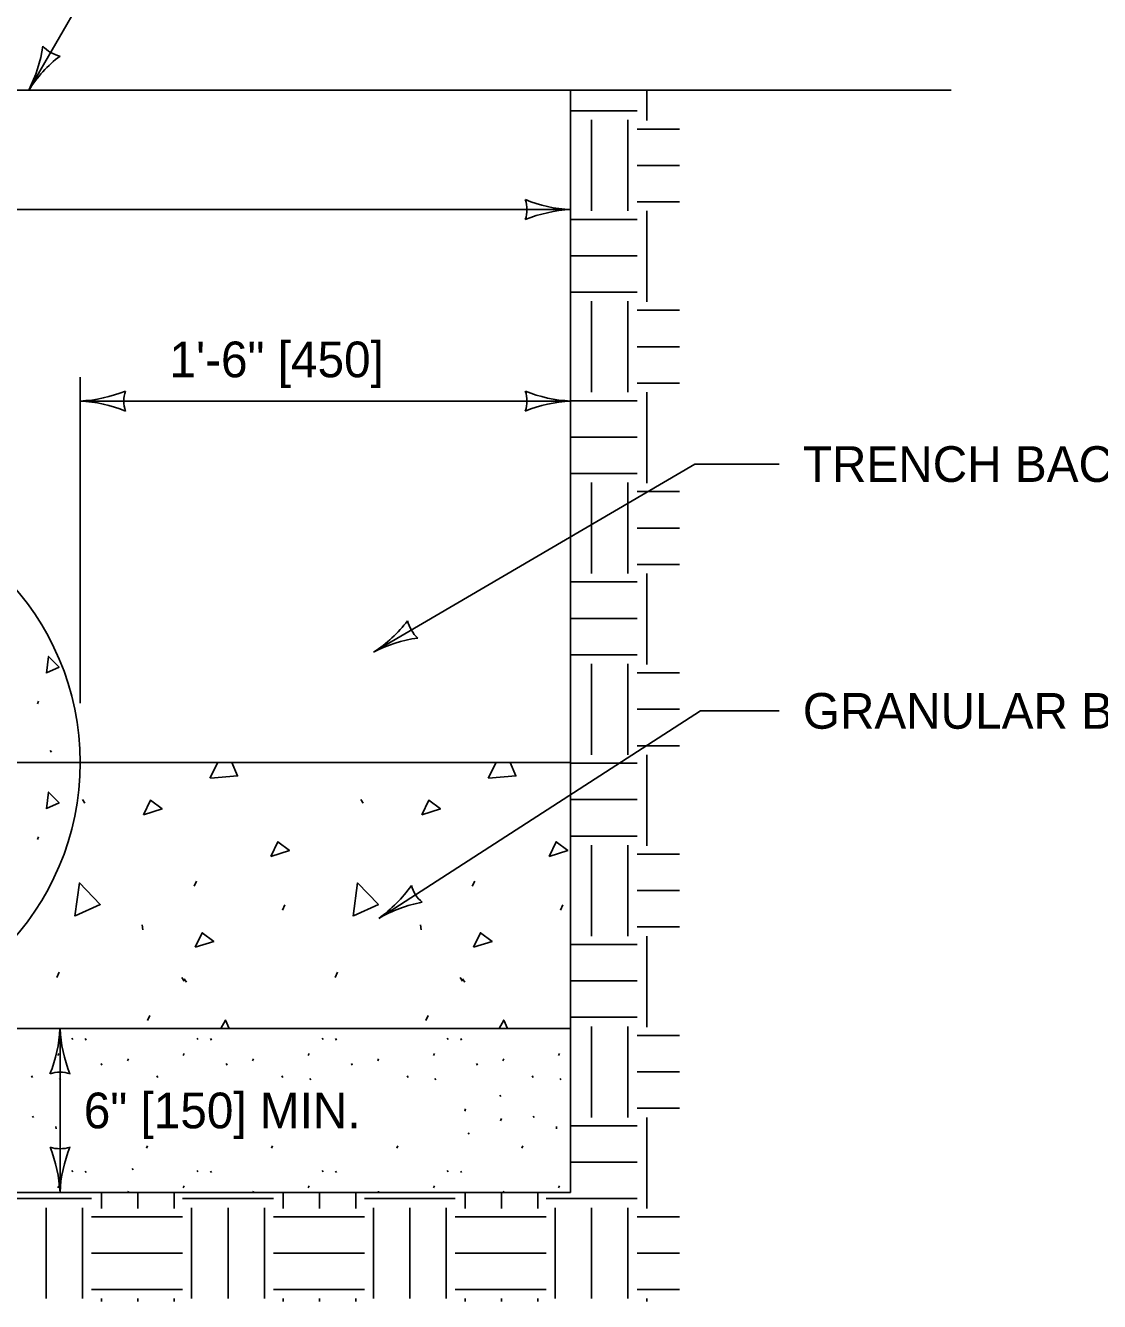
# Model space of a CAD drawing. Extents: x 49991.4 to 50061.4, y 49960.6 to 50011.4.
# Drawn here: x 50008.251 to 50010.057, y 49995.607 to 49997.751 of the extents above; entities that cross this region are included whole.
import ezdxf

# ---------------------------------------------------------------- set-up
doc = ezdxf.new("R2010")
doc.units = 0
for name, color, linetype in [('Level 1', 7, 'Continuous'), ('Level 2', 7, 'Continuous'), ('Level 3', 7, 'Continuous'), ('Level 5', 7, 'Continuous')]:
    doc.layers.add(name, color=color, linetype=linetype)

msp = doc.modelspace()

# ---------------------------------------------------------------- linework, layer by layer
at = {"layer": 'Level 1'}
for p, q in [((50009.8078, 49997.6424), (50005.9845, 49997.6424)), ((50009.1677, 49997.6424), (50009.1677, 49995.7899)), ((50009.296, 49997.6424), (50009.296, 49997.5913)), ((50009.1677, 49997.6076), (50009.2796, 49997.6076)), ((50009.2032, 49997.5923), (50009.2032, 49997.4395)), ((50009.2643, 49997.5923), (50009.2643, 49997.4395)), ((50009.2796, 49997.5771), (50009.351, 49997.5771)), ((50009.2796, 49997.5159), (50009.351, 49997.5159)), ((50009.2796, 49997.4548), (50009.351, 49997.4548)), ((50009.1677, 49997.4252), (50009.2796, 49997.4252)), ((50009.296, 49997.4395), (50009.296, 49997.2866)), ((50009.1677, 49997.3641), (50009.2796, 49997.3641)), ((50009.1677, 49997.3029), (50009.2796, 49997.3029)), ((50009.2032, 49997.2877), (50009.2032, 49997.1348)), ((50009.2643, 49997.2877), (50009.2643, 49997.1348)), ((50009.2796, 49997.2724), (50009.351, 49997.2724)), ((50009.2796, 49997.2112), (50009.351, 49997.2112)), ((50009.2796, 49997.1501), (50009.351, 49997.1501)), ((50009.296, 49997.1348), (50009.296, 49996.9819)), ((50009.1677, 49997.1205), (50009.2796, 49997.1205)), ((50009.1677, 49997.0594), (50009.2796, 49997.0594)), ((50009.1677, 49996.9982), (50009.2796, 49996.9982)), ((50009.2032, 49996.983), (50009.2032, 49996.8301)), ((50009.2643, 49996.983), (50009.2643, 49996.8301)), ((50009.2796, 49996.9677), (50009.351, 49996.9677)), ((50009.2796, 49996.9065), (50009.351, 49996.9065)), ((50009.2796, 49996.8454), (50009.351, 49996.8454)), ((50009.296, 49996.8301), (50009.296, 49996.6772)), ((50009.1677, 49996.8159), (50009.2796, 49996.8159)), ((50009.1677, 49996.7547), (50009.2796, 49996.7547)), ((50009.1677, 49996.6935), (50009.2796, 49996.6935)), ((50009.2032, 49996.6783), (50009.2032, 49996.5254)), ((50009.2643, 49996.6783), (50009.2643, 49996.5254)), ((50009.2796, 49996.663), (50009.351, 49996.663)), ((50008.2713, 49996.6112), (50008.2732, 49996.6156)), ((50009.2796, 49996.6018), (50009.351, 49996.6018)), ((50008.2928, 49996.5325), (50008.2947, 49996.5296)), ((50009.2796, 49996.5407), (50009.351, 49996.5407)), ((50009.296, 49996.5254), (50009.296, 49996.3725)), ((50008.3431, 49996.5122), (50009.1677, 49996.5122)), ((50008.561, 49996.4861), (50008.5748, 49996.5122)), ((50009.0289, 49996.4861), (50009.0427, 49996.5122)), ((50009.1677, 49996.5112), (50009.2796, 49996.5112)), ((50008.3471, 49996.45), (50008.351, 49996.4441)), ((50008.815, 49996.45), (50008.8189, 49996.4441)), ((50009.1677, 49996.45), (50009.2796, 49996.45)), ((50008.2713, 49996.3831), (50008.2732, 49996.3875)), ((50009.1677, 49996.3889), (50009.2796, 49996.3889)), ((50009.2032, 49996.3736), (50009.2032, 49996.2207)), ((50009.2643, 49996.3736), (50009.2643, 49996.2207)), ((50009.2796, 49996.3583), (50009.351, 49996.3583)), ((50008.5346, 49996.3044), (50008.5385, 49996.3132)), ((50009.0025, 49996.3044), (50009.0065, 49996.3132)), ((50009.2796, 49996.2971), (50009.351, 49996.2971)), ((50008.6831, 49996.2644), (50008.687, 49996.2732)), ((50009.151, 49996.2644), (50009.1549, 49996.2732)), ((50008.4474, 49996.2398), (50008.4484, 49996.231)), ((50008.9153, 49996.2398), (50008.9163, 49996.231)), ((50009.2796, 49996.236), (50009.351, 49996.236)), ((50009.1677, 49996.2065), (50009.2796, 49996.2065)), ((50009.296, 49996.2207), (50009.296, 49996.0678)), ((50008.3041, 49996.1511), (50008.308, 49996.1599)), ((50008.772, 49996.1511), (50008.7759, 49996.1599)), ((50008.5141, 49996.1511), (50008.518, 49996.1452)), ((50008.518, 49996.1488), (50008.5219, 49996.143)), ((50008.982, 49996.1511), (50008.9859, 49996.1452)), ((50008.9859, 49996.1488), (50008.9898, 49996.143)), ((50009.1677, 49996.1453), (50009.2796, 49996.1453)), ((50008.4565, 49996.0787), (50008.4604, 49996.0874)), ((50008.9244, 49996.0787), (50008.9283, 49996.0874)), ((50009.1677, 49996.0842), (50009.2796, 49996.0842)), ((50009.1677, 49996.0653), (50006.6247, 49996.0653)), ((50008.3291, 49996.0493), (50008.3307, 49996.0469)), ((50008.5396, 49996.0493), (50008.5412, 49996.0469)), ((50008.75, 49996.0493), (50008.7516, 49996.0469)), ((50008.9605, 49996.0493), (50008.9621, 49996.0469)), ((50009.1677, 49995.7899), (50009.1677, 49996.0653)), ((50009.2032, 49996.0689), (50009.2032, 49995.916)), ((50009.2643, 49996.0689), (50009.2643, 49995.916)), ((50009.2796, 49996.0536), (50009.351, 49996.0536)), ((50008.3517, 49996.0484), (50008.3533, 49996.046)), ((50008.5621, 49996.0484), (50008.5637, 49996.046)), ((50008.7726, 49996.0484), (50008.7742, 49996.046)), ((50008.983, 49996.0484), (50008.9846, 49996.046)), ((50008.3058, 49996.02), (50008.3074, 49996.0235)), ((50008.4225, 49996.0109), (50008.4241, 49996.0144)), ((50008.5163, 49996.02), (50008.5178, 49996.0235)), ((50008.6329, 49996.0109), (50008.6345, 49996.0144)), ((50008.7267, 49996.02), (50008.7283, 49996.0235)), ((50008.8434, 49996.0109), (50008.845, 49996.0144)), ((50008.9372, 49996.02), (50008.9387, 49996.0235)), ((50009.0538, 49996.0109), (50009.0554, 49996.0144)), ((50009.1476, 49996.02), (50009.1492, 49996.0235)), ((50008.2615, 49995.9856), (50008.2631, 49995.9832)), ((50008.3782, 49996.0063), (50008.3798, 49996.0039)), ((50008.4719, 49995.9856), (50008.4735, 49995.9832)), ((50008.5887, 49996.0063), (50008.5902, 49996.0039)), ((50008.6824, 49995.9856), (50008.684, 49995.9832)), ((50008.7991, 49996.0063), (50008.8007, 49996.0039)), ((50008.8928, 49995.9856), (50008.8944, 49995.9832)), ((50009.0096, 49996.0063), (50009.0111, 49996.0039)), ((50009.1033, 49995.9856), (50009.1049, 49995.9832)), ((50009.2796, 49995.9924), (50009.351, 49995.9924)), ((50008.3082, 49995.9813), (50008.3098, 49995.9789)), ((50008.7291, 49995.9813), (50008.7307, 49995.9789)), ((50008.9396, 49995.9813), (50008.9412, 49995.9789)), ((50009.15, 49995.9813), (50009.1516, 49995.9789)), ((50009.0486, 49995.9532), (50009.0502, 49995.9508)), ((50008.9898, 49995.9266), (50008.9913, 49995.9302)), ((50009.2796, 49995.9313), (50009.351, 49995.9313)), ((50008.263, 49995.9181), (50008.2646, 49995.9157)), ((50008.3021, 49995.9005), (50008.3025, 49995.8969)), ((50009.0499, 49995.9104), (50009.0515, 49995.914)), ((50009.1048, 49995.9181), (50009.1064, 49995.9157)), ((50009.1439, 49995.9005), (50009.1443, 49995.8969)), ((50009.1677, 49995.9018), (50009.2796, 49995.9018)), ((50009.296, 49995.916), (50009.296, 49995.7631)), ((50008.9955, 49995.89), (50008.9971, 49995.8876)), ((50008.4545, 49995.8645), (50008.4561, 49995.8681)), ((50008.665, 49995.8645), (50008.6666, 49995.8681)), ((50008.8754, 49995.8645), (50008.877, 49995.8681)), ((50009.0859, 49995.8645), (50009.0875, 49995.8681)), ((50009.1677, 49995.8406), (50009.2796, 49995.8406)), ((50008.3291, 49995.8267), (50008.3307, 49995.8243)), ((50008.3517, 49995.8258), (50008.3533, 49995.8234)), ((50008.4305, 49995.8302), (50008.4321, 49995.8278)), ((50008.5396, 49995.8267), (50008.5412, 49995.8243)), ((50008.5621, 49995.8258), (50008.5637, 49995.8234)), ((50008.75, 49995.8267), (50008.7516, 49995.8243)), ((50008.7726, 49995.8258), (50008.7742, 49995.8234)), ((50008.9605, 49995.8267), (50008.9621, 49995.8243)), ((50008.983, 49995.8258), (50008.9846, 49995.8234)), ((50008.3058, 49995.7974), (50008.3074, 49995.8009)), ((50008.5163, 49995.7974), (50008.5178, 49995.8009)), ((50008.7267, 49995.7974), (50008.7283, 49995.8009)), ((50008.9372, 49995.7974), (50008.9387, 49995.8009)), ((50009.1476, 49995.7974), (50009.1492, 49995.8009)), ((50009.1677, 49995.7899), (50006.6247, 49995.7899)), ((50006.6247, 49995.7899), (50009.1677, 49995.7899)), ((50008.2094, 49995.7795), (50008.3623, 49995.7795)), ((50008.3787, 49995.7899), (50008.3787, 49995.7631)), ((50008.4232, 49995.7899), (50008.4241, 49995.7918)), ((50008.4399, 49995.7899), (50008.4399, 49995.7631)), ((50008.5011, 49995.7899), (50008.5011, 49995.7631)), ((50008.5152, 49995.7795), (50008.6681, 49995.7795)), ((50008.6337, 49995.7899), (50008.6345, 49995.7918)), ((50008.6845, 49995.7899), (50008.6845, 49995.7631)), ((50008.7457, 49995.7899), (50008.7457, 49995.7631)), ((50008.8068, 49995.7899), (50008.8068, 49995.7631)), ((50008.821, 49995.7795), (50008.9739, 49995.7795)), ((50008.8441, 49995.7899), (50008.845, 49995.7918)), ((50008.9903, 49995.7899), (50008.9903, 49995.7631)), ((50009.0514, 49995.7899), (50009.0514, 49995.7631)), ((50009.0546, 49995.7899), (50009.0554, 49995.7918)), ((50009.1126, 49995.7899), (50009.1126, 49995.7631)), ((50009.1267, 49995.7795), (50009.2796, 49995.7795)), ((50008.2859, 49995.7642), (50008.2859, 49995.6113)), ((50008.347, 49995.7642), (50008.347, 49995.6113)), ((50008.5305, 49995.7642), (50008.5305, 49995.6113)), ((50008.5917, 49995.7642), (50008.5917, 49995.6113)), ((50008.6528, 49995.7642), (50008.6528, 49995.6113)), ((50008.8363, 49995.7642), (50008.8363, 49995.6113)), ((50008.8974, 49995.7642), (50008.8974, 49995.6113)), ((50008.9586, 49995.7642), (50008.9586, 49995.6113)), ((50009.142, 49995.7642), (50009.142, 49995.6113)), ((50009.2032, 49995.7642), (50009.2032, 49995.6113)), ((50009.2643, 49995.7642), (50009.2643, 49995.6113)), ((50008.3623, 49995.7489), (50008.5152, 49995.7489)), ((50008.6681, 49995.7489), (50008.821, 49995.7489)), ((50008.9739, 49995.7489), (50009.1267, 49995.7489)), ((50009.2796, 49995.7489), (50009.351, 49995.7489)), ((50008.3623, 49995.6877), (50008.5152, 49995.6877)), ((50008.6681, 49995.6877), (50008.821, 49995.6877)), ((50008.9739, 49995.6877), (50009.1267, 49995.6877)), ((50009.2796, 49995.6877), (50009.351, 49995.6877)), ((50008.3623, 49995.6266), (50008.5152, 49995.6266)), ((50008.6681, 49995.6266), (50008.821, 49995.6266)), ((50008.9739, 49995.6266), (50009.1267, 49995.6266)), ((50009.2796, 49995.6266), (50009.351, 49995.6266)), ((50008.3787, 49995.6113), (50008.3787, 49995.6066)), ((50008.4399, 49995.6113), (50008.4399, 49995.6066)), ((50008.5011, 49995.6113), (50008.5011, 49995.6066)), ((50008.6845, 49995.6113), (50008.6845, 49995.6066)), ((50008.7457, 49995.6113), (50008.7457, 49995.6066)), ((50008.8068, 49995.6113), (50008.8068, 49995.6066)), ((50008.9903, 49995.6113), (50008.9903, 49995.6066)), ((50009.0514, 49995.6113), (50009.0514, 49995.6066)), ((50009.1126, 49995.6113), (50009.1126, 49995.6066)), ((50009.296, 49995.6113), (50009.296, 49995.6066))]:
    msp.add_line(p, q, dxfattribs=at)
for points in [[(50008.2863, 49996.6628), (50008.2901, 49996.6907), (50008.3076, 49996.6727), (50008.2867, 49996.663)], [(50008.598, 49996.5122), (50008.6079, 49996.49), (50008.562, 49996.4861)], [(50009.0659, 49996.5122), (50009.0758, 49996.49), (50009.0299, 49996.4861)], [(50008.2863, 49996.4347), (50008.2901, 49996.4626), (50008.3076, 49996.4445), (50008.2867, 49996.4349)], [(50008.4496, 49996.4246), (50008.4613, 49996.449), (50008.4809, 49996.4343), (50008.4496, 49996.4246)], [(50008.9175, 49996.4246), (50008.9293, 49996.449), (50008.9488, 49996.4343), (50008.9175, 49996.4246)], [(50008.6638, 49996.3547), (50008.6755, 49996.3792), (50008.695, 49996.3645), (50008.6638, 49996.3547)], [(50009.1317, 49996.3547), (50009.1434, 49996.3792), (50009.1629, 49996.3645), (50009.1317, 49996.3547)], [(50008.334, 49996.2543), (50008.3418, 49996.3101), (50008.3768, 49996.274), (50008.3349, 49996.2546)], [(50008.8019, 49996.2543), (50008.8097, 49996.3101), (50008.8447, 49996.274), (50008.8029, 49996.2546)], [(50008.5366, 49996.2019), (50008.5483, 49996.2263), (50008.5678, 49996.2116), (50008.5366, 49996.2019)], [(50009.0045, 49996.2019), (50009.0162, 49996.2263), (50009.0358, 49996.2116), (50009.0045, 49996.2019)], [(50008.5798, 49996.0653), (50008.5874, 49996.0796), (50008.5938, 49996.0653)], [(50009.0477, 49996.0653), (50009.0553, 49996.0796), (50009.0617, 49996.0653)]]:
    msp.add_lwpolyline(points, dxfattribs=at)
msp.add_circle((50007.8962, 49996.5122), 0.4469, dxfattribs=at)
at = {"layer": 'Level 3'}
for p, q in [((50008.2567, 49997.6424), (50008.4268, 49997.9363)), ((50006.6247, 49997.4417), (50009.1677, 49997.4417)), ((50008.3431, 49996.6122), (50008.3431, 49997.1599)), ((50009.1677, 49997.1199), (50008.3431, 49997.1199)), ((50008.8366, 49996.6978), (50009.3768, 49997.014)), ((50009.5183, 49997.014), (50009.3768, 49997.014)), ((50008.8453, 49996.2504), (50009.3863, 49996.5992)), ((50009.5183, 49996.5992), (50009.3863, 49996.5992)), ((50008.3092, 49995.7899), (50008.3092, 49996.0653))]:
    msp.add_line(p, q, dxfattribs=at)
for centre, radius, start, end in [((50008.0495, 49997.749), 0.233, 332.7656, 352.0154), ((50008.3209, 49997.7533), 0.0548, 222.0771, 257.7994), ((50008.4443, 49997.5232), 0.2223, 127.3943, 147.5778), ((50009.1769, 49997.6638), 0.2223, 247.456, 267.6395), ((50009.0395, 49997.4417), 0.0548, 342.1388, 17.8612), ((50009.1792, 49997.209), 0.233, 92.8273, 112.0772), ((50008.3316, 49997.3526), 0.233, 272.8273, 292.0772), ((50008.4713, 49997.1199), 0.0548, 162.1388, 197.8612), ((50009.1769, 49997.3421), 0.2223, 247.456, 267.6395), ((50009.0395, 49997.1199), 0.0548, 342.1388, 17.8612), ((50008.3339, 49996.8978), 0.2223, 67.456, 87.6395), ((50009.1792, 49996.8872), 0.233, 92.8273, 112.0772), ((50008.7091, 49996.8928), 0.233, 303.1723, 322.4222), ((50008.9473, 49996.7625), 0.0548, 192.4838, 228.2062), ((50008.9409, 49996.5014), 0.2223, 97.801, 117.9845), ((50008.7095, 49996.4398), 0.233, 305.6416, 324.8914), ((50008.9531, 49996.3199), 0.0548, 194.9531, 230.6755), ((50008.958, 49996.0588), 0.2223, 100.2703, 120.4538), ((50008.087, 49996.0744), 0.2223, 337.456, 357.6395), ((50008.5419, 49996.0768), 0.233, 182.8273, 202.0772), ((50008.3092, 49995.9371), 0.0548, 72.1388, 107.8612), ((50008.3092, 49995.9181), 0.0548, 252.1388, 287.8612), ((50008.0765, 49995.7784), 0.233, 2.8273, 22.0772), ((50008.5313, 49995.7807), 0.2223, 157.456, 177.6395)]:
    msp.add_arc(centre, radius, start, end, dxfattribs=at)
at = {"layer": 'Level 5'}
msp.add_line((50007.3493, 49996.5122), (50008.4431, 49996.5122), dxfattribs=at)

# ---------------------------------------------------------------- texts
at = {"layer": 'Level 2'}
for s, p in [('1\'-6" [450]', (50008.4933, 49997.1599)), ('TRENCH BACKFILL  1', (50009.5583, 49996.984)), ('GRANULAR BEDDING  2', (50009.5583, 49996.5692)), ('6" [150] MIN.', (50008.3492, 49995.8976))]:
    msp.add_text(s, height=0.06, dxfattribs=at).set_placement(p)

doc.saveas('drawing.dxf')
